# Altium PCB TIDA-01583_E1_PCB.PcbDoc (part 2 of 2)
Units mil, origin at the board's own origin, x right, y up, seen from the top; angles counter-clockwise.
Board outline 2000 x 2400 mil, 4 copper layers (Top Layer, GND, PWR, Bottom Layer), stack 5.6 mil thick; 127 components, 58 nets, 301 pads, 119 vias.
Unrouted connection lines stored in the file: 16.
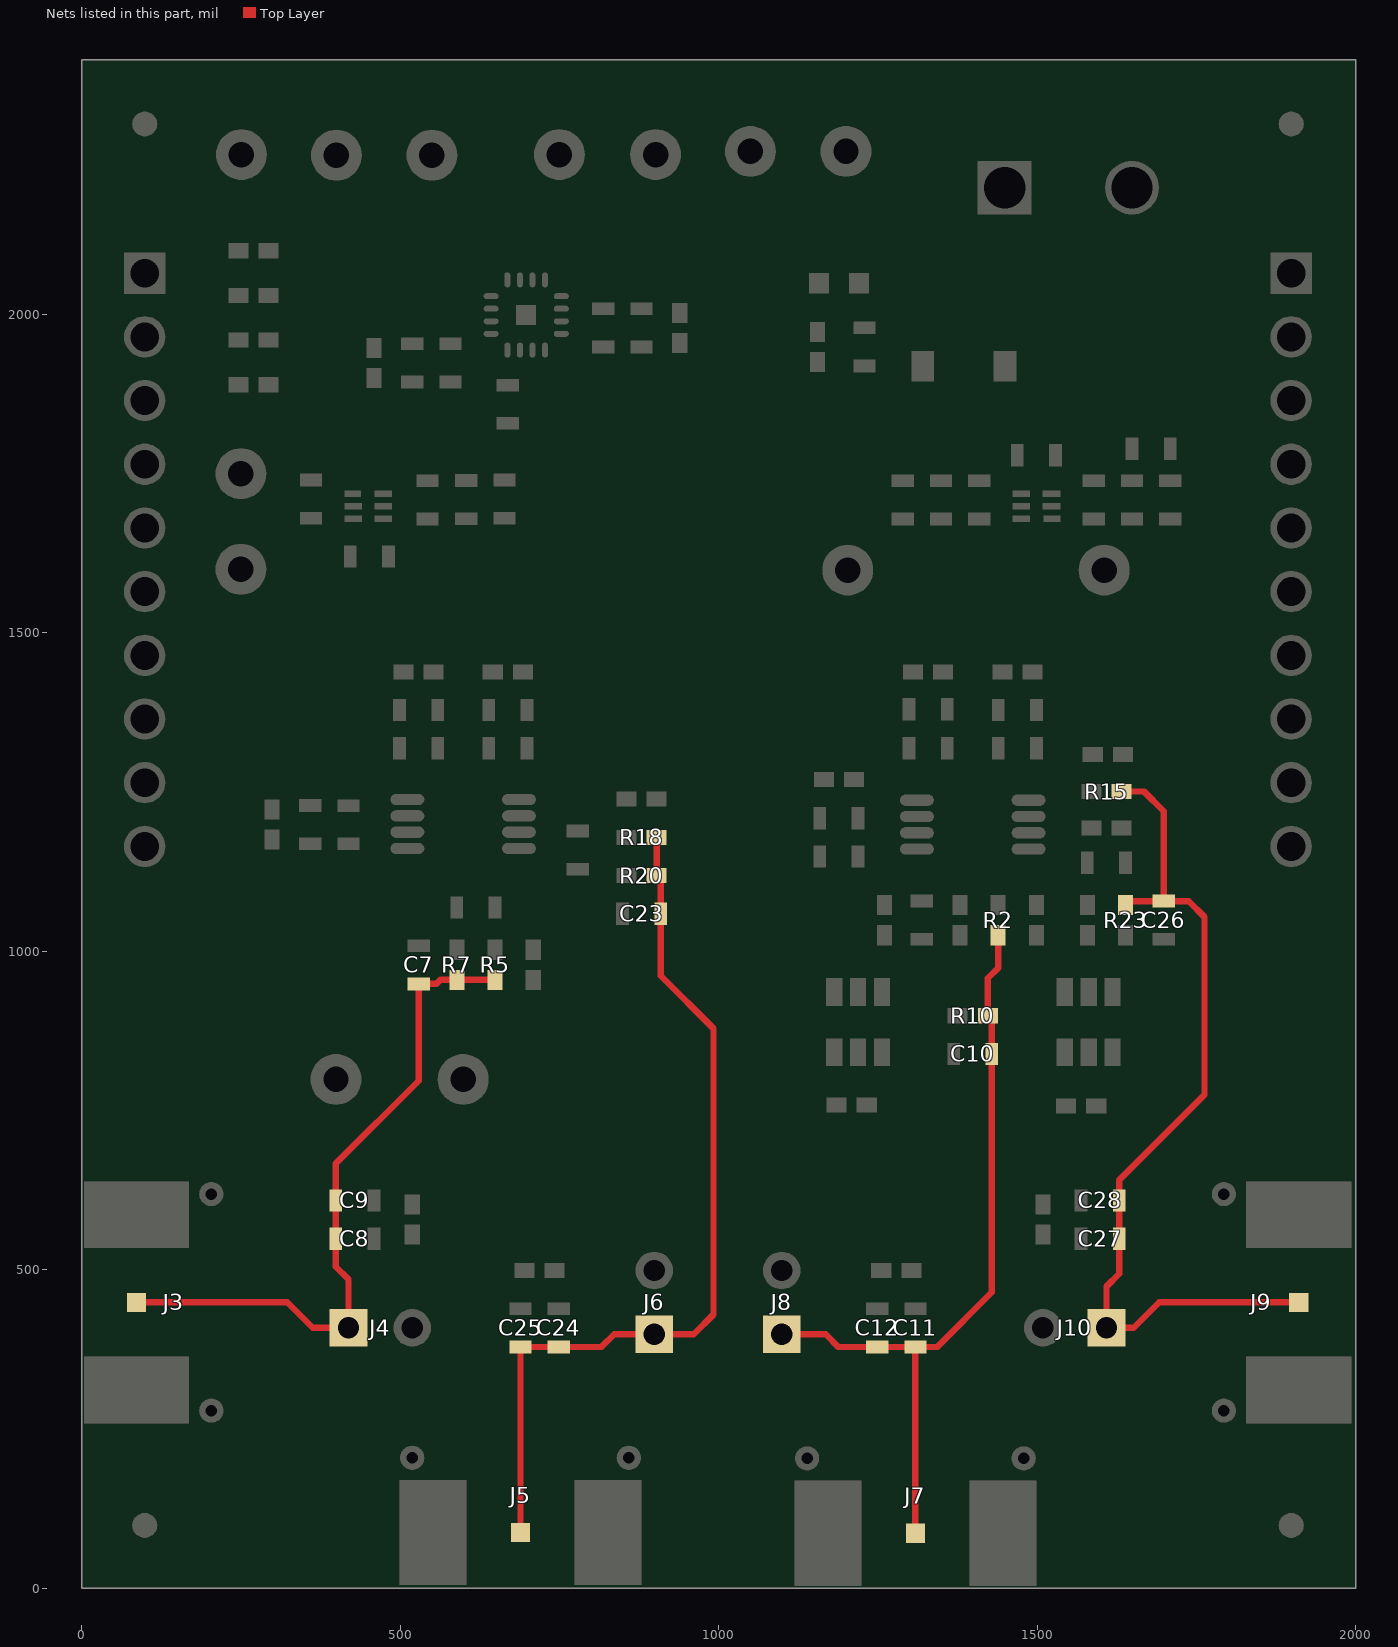
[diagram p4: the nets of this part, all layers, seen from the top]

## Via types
v1: diameter 24, hole 12, Top Layer to Bottom Layer, tented both sides, 118 vias
v2: diameter 19.68, hole 7.87, Top Layer to Bottom Layer, 1 vias

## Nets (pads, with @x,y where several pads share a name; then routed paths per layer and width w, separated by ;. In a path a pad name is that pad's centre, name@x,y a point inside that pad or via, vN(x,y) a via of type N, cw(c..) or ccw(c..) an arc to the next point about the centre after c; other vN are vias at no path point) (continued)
VOUT1: C7.1 C8.1 C9.1 J3.1 J4.1 R5.2 R7.2 | length 1074.3
  Top Layer w10: J3.1@86,448.99 323,448.99 363,408.99 J4.1@419,408.99 419,484.99 399,504.99 C8.1@399,548.99 C9.1@399,608.99 399,666.99 529,796.99 C7.1@529,948.99 557,948.99 563.38,955.37 R7.2@589,955.37 R5.2@649,955.37
VOUT2: C23.1 C24.1 C25.1 J5.1 J6.1 R18.2 R20.2 | length 1401.6
  Top Layer w10: J5.1@689,87.49 C25.1@689,378.99 C24.1@749,378.99 816,378.99 836,398.99 J6.1@899,398.99 961,398.99 992,429.99 992,878.99 909,961.99 C23.1@909,1058.99 909,1112.61 R20.2@902.62,1118.99 R18.2@902.62,1178.99
VOUT3: C10.1 C11.1 C12.1 J7.1 J8.1 R2.2 R10.2 | length 1236.2
  Top Layer w10: J8.1@1099,398.99 1168,398.99 1188,378.99 C12.1@1249,378.99 C11.1@1309,378.99 ; J7.1@1309,86.49 C11.1@1309,378.99 ; R2.2@1439,1025.37 1439,973.99 1422.62,957.61 R10.2@1422.62,898.99 1429,892.61 C10.1@1429,838.99 1429,464.99 1343,378.99 C11.1@1309,378.99
VOUT4: C26.1 C27.1 C28.1 J9.1 J10.1 R15.2 R23.2 | length 1384.4
  Top Layer w10: R15.2@1632.62,1251.02 1667.98,1251.02 1699,1219.99 C26.1@1699,1078.99 ; R23.2@1639,1072.61 1645.38,1078.99 C26.1@1699,1078.99 ; J9.1@1910.86,448.99 1692,448.99 1652,408.99 J10.1@1609,408.99 1609,473.99 1629,493.99 C27.1@1629,548.99 C28.1@1629,608.99 1629,640.99 1762.94,774.93 1762.94,1054.06 1738,1078.99 C26.1@1699,1078.99
pads on no net: FID1.1 FID2.1 FID3.1 FID4.1 J1.1 J1.2 J1.5 J1.7 J1.9 J1.10 J2.2 J2.3 J2.4 J2.5 J2.6 J2.7 J2.8 J2.9 J2.10 J3. J5. J7. J9. LBL1.0

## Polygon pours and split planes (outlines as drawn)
+6V5_IN on Top Layer "Top Layer-GND" (solid, pour order 49): 1132,1941.99 1273,1941.99 1281,1949.99 1317,1949.99 1340,1949.99 1349,1940.99 1370,1919.99 1370,1753.99 1370,1728.99 1365,1723.99 1324,1723.99 1152,1723.99 1112,1763.99 1112,1870.99 1112,1921.99 1132,1941.99
NetD2_2 on Top Layer "Top Layer-GND" (solid, pour order 50): 1128,2074.99 1128,1968.99 1139,1957.99 1140,1956.99 1161,1956.99 1167,1956.99 1178,1967.99 1178,1997.99 1178,2072.55 1174,2076.55 1167.56,2082.99 1142,2082.99 1136,2082.99
NetD1_2 on Top Layer "Top Layer-GND" (solid, pour order 51): 1399,2250.99 1399,1913.99 1426,1886.99 1491,1886.99 1502,1897.99 1506,1901.99 1506,2016.99 1506,2246.99 1497,2255.99 1489,2263.99 1454,2263.99 1412,2263.99 1399,2250.99
+6V5A on Top Layer "Top Layer-GND" (solid, pour order 52): 1455,1728.99 1485,1728.99 1489,1724.99 1490,1723.99 1490,1719.99 1490,1713.99 1489,1712.99 1485,1712.99 1449.99,1712.99 1445,1708 1445,1694.99 1445,1688.99 1449,1684.99 1449.76,1684.23 1461,1684.23 1489.76,1684.23 1491,1682.99 1492,1681.99 1492,1677.99 1492,1675.99 1490,1673.99 1482,1673.99 1446,1673.99 1434,1661.99 1432,1659.99 1371,1659.99 1336,1659.99 1326,1669.99 1326,1690.99 1329,1693.99 1331,1695.99 1350,1695.99 1412,1695.99 1445,1728.99
+5V0A_OUT on Top Layer "Top Layer-GND" (solid, pour order 53): 1512,1681.99 1557,1681.99 1566,1690.99 1571,1695.99 1598,1695.99 1666,1695.99 1672,1689.99 1673,1688.99 1673,1664.99 1673,1663.99 1666,1656.99 1663,1653.99 1604,1653.99 1519,1653.99 1512,1660.99
DAC_VDD on Top Layer "Top Layer-GND" (solid, pour order 56): 745,2013.99 792,2013.99 801,2022.99 814,2035.99 939,2035.99 946.5,2035.99 959.5,2022.99 959.5,1990.49 952,1982.99 913,1982.99 905,1990.99 903,1992.99 875,1992.99 776,1992.99 765,2003.99 740.62,2003.99 739,2005.61 739,2008.99 739,2011.99 741,2013.99 746,2013.99
OPA_VCC2 on Top Layer "Top Layer-GND" (solid, pour order 58): 1336.15,1167.99 1340,1164.14 1340,1148.99 1320,1128.99 1242,1128.99 1211,1128.99 1207,1132.99 1206,1133.99 1206,1226.99 1206,1243.99 1195,1254.99 1194,1255.99 1194,1284.99 1194,1290.99 1196,1292.99 1201,1297.99 1213,1297.99 1240,1297.99 1247,1290.99 1250,1287.99 1250,1256.99 1250,1190.99 1269,1171.99 1273,1167.99
OPA_VCC1 on Top Layer "Top Layer-GND" (solid, pour order 59): 537,1168.99 542,1163.99 542,1152.99 540,1150.99 528.32,1139.31 415,1139.31 284.68,1139.31 273,1150.99 273,1186.99 278,1191.99 280,1193.99 311,1193.99 317,1193.99 330,1180.99 347,1180.99 455,1180.99 467,1168.99
DAC_VIO on Top Layer "Top Layer-GND" (solid, pour order 64): 633,1974.99 652,1974.99 655,1971.99 655,1964.99 652,1961.99 631,1940.99 593,1940.99 487,1940.99 477,1930.99 453,1930.99 447,1930.99 443,1934.99 443,1964.99 447,1968.99 453,1974.99 624,1974.99
GND on Top Layer "Top Layer-GND" (solid, pour order 66): 509,1905.99 611,1905.99 624,1892.99 629,1887.99 629,1862.99 629,1853.99 612,1836.99 583,1836.99 507,1836.99 498,1845.99 498,1865.99 498,1894.99
GND on Top Layer "Top Layer-GND" (solid, pour order 67): 801,1960.99 899,1960.99 902,1957.99 902,1926.99 902,1888.99 893,1879.99 889,1875.99 856,1875.99 812,1875.99 800,1887.99 796,1891.99 796,1915.99 796,1955.99 801,1960.99
GND on Top Layer "Top Layer-GND" (solid, pour order 69): 1205,2092.99 1205,1973.99 1213,1965.99 1273,1965.99 1281,1973.99 1286,1978.99 1286,2034.99 1286,2089.99 1278,2097.99 1270,2105.99 1238,2105.99 1218,2105.99 1205,2092.99
GND on Top Layer "Top Layer-GND" (solid, pour order 70): 1220,1694.99 1304,1694.99 1310,1688.99 1310,1639.99 1303,1632.99 1302,1631.99 1272,1631.99 1253,1631.99 1231,1653.99 1215,1669.99 1215,1681.99 1215,1689.99
GND on Top Layer "Top Layer-GND" (solid, pour order 73): 1571,1808.99 1571,1728.99 1574,1725.99 1606,1725.99 1611,1730.99 1611,1755.99 1625,1769.99 1646,1769.99 1657.97,1769.99 1661.97,1773.99 1661.97,1809.99 1658.97,1812.99 1646.97,1824.99 1605.41,1824.99 1581,1824.99 1571,1814.99
+5V0A on Top Layer "Top Layer-GND" (solid, pour order 55): 1628,1749.99 1628,1730.61 1632.62,1725.99 1634.62,1723.99 1654,1723.99 1774,1723.99 1784,1733.99 1784,1811.99 1769,1826.99 1714,1826.99 1697,1809.99 1696,1808.99 1696,1790.99 1696,1769.99 1688,1761.99 1680,1753.99 1632,1753.99
GND on Top Layer "Top Layer-GND" (solid, pour order 74): 1690,1689.99 1690,1637.99 1700,1627.99 1742,1627.99 1754,1639.99 1754,1685.99 1745,1694.99 1720,1694.99 1695,1694.99
GND on Top Layer "Top Layer-GND" (solid, pour order 78): 1311,1398.99 1311,1299.99 1304,1292.99 1267.34,1292.99 1242,1318.33 1242,1342.99 1242,1390.61 1255.38,1403.99 1257.38,1405.99 1289,1405.99 1304,1405.99
GND on Top Layer "Top Layer-GND" (solid, pour order 85): 1618,1346.99 1618,1295.99 1622,1291.99 1624,1289.99 1664.97,1289.99 1675,1289.99 1683,1297.99 1685,1299.99 1685,1331.99 1685,1346.99 1682,1349.99 1672,1359.99 1654,1359.99 1626,1359.99 1619,1352.99 1618,1351.99 1618,1346.99
GND on Top Layer "Top Layer-GND" (solid, pour order 77): 1171,1227.64 1171,1128.64 1164,1121.64 1114.35,1121.64 1102,1133.99 1102,1171.64 1102,1219.27 1115.38,1232.64 1117.38,1234.64 1149,1234.64 1164,1234.64
GND on Top Layer "Top Layer-GND" (solid, pour order 76): 511,1397.64 511,1298.64 504,1291.64 454.35,1291.64 442,1303.99 442,1341.64 442,1389.27 455.38,1402.64 457.38,1404.64 489,1404.64 504,1404.64
GND on Top Layer "Top Layer-GND" (solid, pour order 75): 437.65,1216.84 338.65,1216.84 338.65,1274.64 349.84,1285.84 381.65,1285.84 429.27,1285.84 442.65,1272.46 444.65,1270.46 444.65,1238.84 444.65,1223.84
GND on Top Layer "Top Layer-GND" (solid, pour order 86): 685,1398.99 685,1286.99 670,1271.99 660,1261.99 660,1249.99 660,1240.99 667,1233.99 788.16,1233.99 793,1238.84 793,1278.99 793,1367.99 765,1395.99 755,1405.99 720,1405.99 692,1405.99
GND on Top Layer "Top Layer-GND" (solid, pour order 84): 886,1276.99 886,1225.99 890,1221.99 892,1219.99 932.97,1219.99 943,1219.99 951,1227.99 953,1229.99 953,1261.99 953,1276.99 950,1279.99 940,1289.99 922,1289.99 894,1289.99 887,1282.99 886,1281.99 886,1276.99
GND on Top Layer "Top Layer-GND" (solid, pour order 83): 865.62,1020.99 865.62,1071.99 861.62,1075.99 859.62,1077.99 818.65,1077.99 808.62,1077.99 800.62,1069.99 798.62,1067.99 798.62,1035.99 798.62,1020.99 801.62,1017.99 811.62,1007.99 829.62,1007.99 857.62,1007.99 864.62,1014.99 865.62,1015.99 865.62,1020.99
GND on Top Layer "Top Layer-GND" (solid, pour order 82): 491,992.37 542,992.37 546,996.37 548,998.37 548,1039.34 548,1049.37 540,1057.37 538,1059.37 506,1059.37 491,1059.37 488,1056.37 478,1046.37 478,1028.37 478,1000.37 485,993.37 486,992.37 491,992.37
GND on Top Layer "Top Layer-GND" (solid, pour order 81): 747,971.99 696,971.99 692,967.99 690,965.99 690,925.02 690,914.99 698,906.99 700,904.99 732,904.99 747,904.99 750,907.99 760,917.99 760,935.99 760,963.99 753,970.99 752,971.99 747,971.99
GND on Top Layer "Top Layer-GND" (solid, pour order 87): 1494,1404.64 1540.62,1404.64 1556,1389.27 1556,1305.99 1536,1285.99 1521,1270.99 1521,1249.99 1521,1239.99 1513,1231.99 1466,1231.99 1458,1239.99 1458,1268.99 1465,1275.99 1487,1297.99 1487,1298.64 1487,1397.64
GND on Top Layer "Top Layer-GND" (solid, pour order 88): 1352,858.8 1383,858.8 1387,854.8 1388,853.8 1388,833.8 1388,765.99 1375,752.99 1360.31,752.99 1348,765.31 1348,840.56 1348,854.8
GND on Top Layer "Top Layer-GND" (solid, pour order 80): 1270.62,775.61 1219.62,775.61 1215.62,771.61 1213.62,769.61 1213.62,728.65 1213.62,718.61 1221.62,710.61 1223.62,708.61 1255.62,708.61 1270.62,708.61 1273.62,711.61 1283.62,721.61 1283.62,739.61 1283.62,767.61 1276.62,774.61 1275.62,775.61 1270.62,775.61
GND on Top Layer "Top Layer-GND" (solid, pour order 79): 1630.94,773.8 1579.94,773.8 1575.94,769.8 1573.94,767.8 1573.94,726.84 1573.94,716.8 1581.94,708.8 1583.94,706.8 1615.94,706.8 1630.94,706.8 1633.94,709.8 1643.94,719.8 1643.94,737.8 1643.94,765.8 1636.94,772.8 1635.94,773.8 1630.94,773.8
GND on Top Layer "Top Layer-GND" (solid, pour order 89): 443,638.99 443,528.99 449,522.99 476,522.99 482,528.99 482,533.99 482,571.99 492,581.99 495,584.99 520,584.99 539,584.99 545,590.99 556,601.99 556,635.99 556,667.99 545,678.99 481,678.99 454,678.99 443,667.99
GND on Top Layer "Top Layer-GND" (solid, pour order 90): 769,452.99 769,426.99 764,421.99 634,421.99 603,452.99 603,557.29 623.71,577.99 677,577.99 699,577.99 711,565.99 713,563.99 713,516.99 713,472.99 727,458.99 728,457.99 754,457.99 764,457.99
GND on Top Layer "Top Layer-GND" (solid, pour order 91): 1229,454.99 1229,429.99 1237,421.99 1350,421.99 1367,438.99 1383,454.99 1383,514.99 1383,556.99 1356,583.99 1352,587.99 1307,587.99 1291.62,587.99 1281.62,577.99 1281.62,477.61 1281,476.99 1263,458.99 1246,458.99 1233,458.99
GND on Top Layer "Top Layer-GND" (solid, pour order 92): 1481,589.99 1487,583.99 1522,583.99 1545,583.99 1552,576.99 1554,574.99 1554,553.99 1554,530.99 1563,521.99 1582,521.99 1591,530.99 1592,531.99 1592,570.99 1592,666.93 1573.94,684.99 1569.94,688.99 1529,688.99 1490,688.99 1481,679.99
+5V0A on Top Layer "Top Layer-GND" (solid, pour order 62): 1567.97,954.96 1567.97,814.99 1583.97,798.99 1654.97,798.99 1658.97,798.99 1671.97,811.99 1682,822.02 1682,943.37 1664.38,960.99 1574,960.99
+5V0A on Top Layer "Top Layer-GND" (solid, pour order 61): 1206,958.99 1206,812.99 1214,804.99 1220,798.99 1222,798.99 1293,798.99 1297,798.99 1310,811.99 1316,817.99 1316,949.99 1299,966.99 1214,966.99
+5V0A on Top Layer "Top Layer-GND" (solid, pour order 96): 925,1967.99 994,1967.99 999,1962.99 1000,1961.99 1000,1926.99 1000,1904.99 989,1893.99 984.65,1889.64 956,1889.64 934.35,1889.64 925,1898.99 922,1901.99 922,1937.99 922,1964.99
+5V0A on Top Layer "Top Layer-GND" (solid, pour order 95): 313,1209.99 244,1209.99 239,1214.99 238,1215.99 238,1250.99 238,1272.99 249,1283.99 253.35,1288.35 282,1288.35 303.65,1288.35 313,1278.99 316,1275.99 316,1239.99 316,1212.99
+5V0A on Top Layer "Top Layer-GND" (solid, pour order 94): 1176.24,1257.24 1110.38,1257.24 1105.38,1262.24 1104.38,1263.24 1104.38,1298.24 1104.38,1320.24 1115.38,1331.24 1119.73,1335.59 1148.38,1335.59 1170.02,1335.59 1179.38,1326.24 1179.38,1260.37
GND on Top Layer "Top Layer-GND" (solid, pour order 71): 1386,1812.99 1386,1730.99 1390,1726.99 1421,1726.99 1452,1757.99 1463,1757.99 1480,1757.99 1483,1760.99 1486.6,1764.59 1486.6,1787.99 1486.6,1820.39 1480,1826.99 1473,1833.99 1416,1833.99 1396,1833.99 1387,1824.99 1386,1823.99 1386,1813.99
GND on Top Layer "Top Layer-GND" (solid, pour order 72): 375,1690 372,1693 343,1693 338,1688 338,1663 324,1649 308,1649 304,1645 304,1601 311,1594 343.59,1594 368,1594 375,1601
+6V5A2 on Top Layer "Top Layer-GND" (solid, pour order 54): 459,1728 459,1715 461,1713 467,1713 497,1713 499,1711 499,1687.39 496.6,1684.99 458.99,1684.99 458,1684 458,1674 459,1673 461,1671 475,1671 501,1671 513,1683 513,1715 523,1725 619,1725 623,1729 623,1757 618,1762 610,1770 514,1770 482,1770 465,1753 459,1747
GND on Top Layer "Top Layer-GND" (solid, pour order 57): 527,1688 527,1656 512,1641 491,1641 466,1641 463,1638 463,1598 466,1595 469,1592 512,1592 555,1592 568,1605 568,1634 568,1687 560,1695 558,1697 536,1697
+6V5_IN on Top Layer "Top Layer-GND" (solid, pour order 60): 584,1693 584,1624 600,1608 606,1602 670,1602 698,1602 709,1613 712,1616 712,1651.99 712,1687 706,1693 699,1700 689,1700 591,1700 584,1693
+3V3D on Top Layer "Top Layer-GND" (solid, pour order 68): 411,1917 472,1917 475,1914 477,1912 477,1877 477,1819.62 438.19,1780.81 438.19,1713.76 344,1713.76 329,1729 329,1778 341,1790 380,1829 380,1840 380,1886
GND on GND "Top Layer-GND" (solid, pour order 93): 77,-0.01 1908,-0.01 1998,89.99 1998,2291.94 1891,2398.94 104.9,2398.94 -0.04,2293.99 -0.98,2293.06 -0.98,77.97
+6V5_IN on PWR "Top Layer-GND" (solid, pour order 63): 1105,1895 1252,1895 1270,1877 1270,1754 1236,1720 1209,1693 1129,1693 1113,1693 992,1572 931,1511 751,1511 628,1511 583,1556 578,1561 578,1632 578,1658 606,1686 614,1694 659,1694 891.75,1694 1092.75,1895 1106,1895
+5V0A on PWR "Top Layer-GND" (solid, pour order 65): 916,1987 916,1898 942,1872 994,1872 1007,1885 1064,1942 1293,1942 1341,1894 1352,1883 1352,1660 1352,1573 1213,1434 335,1434 212,1311 212,985 304,893 316,881 549,881 1018,881 1208,691 1631,691 1681,691 1737,747 1829,839 1829,1030 1829,2048 1748,2129 1746,2131 1346,2131 979,2131 919,2071 916,2068 916,1986

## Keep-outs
Keep-Out Layer:
  the board outline again, w11.81

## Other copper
Top Layer:
  text ".Layer_Name" at 426,-1438.24 h60
GND:
  text ".Layer_Name" at 429,-1442.75 h60
PWR:
  text ".Layer_Name" at 429,-1437.75 h60
Bottom Layer:
  text ".Layer_Name" at 426,-1438.24 h60

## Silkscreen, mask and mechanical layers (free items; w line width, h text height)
Top Overlay:
  lines w6: 494,1659 540,1613 744.01,1613 764.01,1633 ; 689,1762 700,1773 895,1773 935,1733 ; 765,899.99 877,1011.99 1227,1011.99 ; 1112,933.99 1112,943.99 1147,978.99 1666,978.99 1684,996.99 ; 1500.51,1472.98 1500.51,1485.5 1522,1506.99 1549,1506.99 ; 1522,1337.99 1542,1337.99 1571,1366.99
  text ".Layer_Name" at 426,-1438.24 h60
Bottom Overlay:
  rectangle: 337,627 637,727
  text "TIDA-" at 937,645 h60
  text "E1" at 314,643 h60
  text ".Layer_Name" at 426,-1438.24 h60
Top Paste:
  text ".Layer_Name" at 426,-1438.24 h60
Bottom Paste:
  text ".Layer_Name" at 426,-1438.24 h60
Top Solder:
  text ".Layer_Name" at 426,-1438.24 h60
  text ".Layer_Name" at 426,-1438.24 h60
Bottom Solder:
  text ".Layer_Name" at 426,-1438.24 h60
Drill Guide:
  text ".Layer_Name" at 426,-1438.24 h60
M1 Board Outline:
  the board outline again, w11.81
M2 Board Dimensions:
  rectangle: -151,-854.75 -26,-729.75
  rectangle: -26,-979.75 349,-854.75
  lines w7: -151,-854.75 849,-854.75 ; -26,-979.75 -26,-729.75 ; 99,-979.75 99,-729.75 ; 349,-979.75 349,-729.75 ; 599,-979.75 599,-729.75 ; -151,-979.75 849,-979.75 849,-729.75 -151,-729.75 -151,-979.75
M3 3D STEP Top:
  text ".Layer_Name" at 426,-1438.24 h60
M4 3D STEP Bottom:
  text ".Layer_Name" at 426,-1438.24 h60
M5 Assembly Top:
  lines w10: -443,-1509.91 6157,-1509.91 ; -443,-1306.58 6159,-1306.58 ; -443,-1103.25 -443,-1713.25 3562,-1713.25 6159,-1713.25 6159,-1103.25 -442.5,-1103.25 -442.5,-1713.25 1133,-1713.25 ; 2022,-1713.25 2022,-1103.25 ; 3289,-1306.58 3289,-1103.25 ; 4129,-1306.58 4129,-1103.25 ; 4751,-1719.75 4751,-1516.91
  text "COMPONENTS MARKED 'DNP' SHOULD NOT BE POPULATED." at 1002.5,-898.25 h60
  text "ASSEMBLY VARIANT:" at 1002,-1013.75 h60
  text ".VariantName" at 2038,-1013.75 h60
  text "PCB VIEWED FROM TOP SIDE" at -379.5,-1235.41 h60
  text "BOARD #:" at 2097,-1235.41 h60
  text ".PRJ_Number" at 2642.5,-1235.41 h60
  text "REV:" at 3487,-1235.41 h60
  text ".PCB_Rev" at 3778.5,-1235.41 h60
  text "SVN REV:" at 4325,-1235.41 h60
  text ".VersionControl_RevNumber" at 4831,-1235.41 h60
  text ".Layer_Name" at 432,-1437.75 h60
  text "LAYER NAME =" at -380,-1438.75 h60
  text "TID #:" at 2097,-1438.75 h60
  text ".TID" at 2642.5,-1438.75 h60
  text "PLOT NAME =" at -379.5,-1644.08 h60
  text ".plot_File_Name" at 426,-1644.08 h60
  text "GENERATED    :" at 2099,-1644.08 h60
  text ".Print_Date" at 2968.5,-1644.08 h60
  text ".Print_Time" at 3697.5,-1644.08 h60
  text "TEXAS INSTRUMENTS" at 4962,-1644.08 h60
M6 Assembly Bottom:
  lines w10: -443.5,-1307.08 6158.5,-1307.08 ; -441.5,-1510.41 6158.5,-1510.41 ; 964.5,-1720.25 964.5,-1517.41 ; 1586.5,-1307.08 1586.5,-1103.75 ; 2426.5,-1307.08 2426.5,-1103.75 ; 3693.5,-1713.75 3693.5,-1103.75 ; 4582.5,-1713.75 6158,-1713.75 6158,-1103.75 -443.5,-1103.75 -443.5,-1713.75 2153.5,-1713.75 6158.5,-1713.75 6158.5,-1103.75
  text "COMPONENTS MARKED 'DNP' SHOULD NOT BE POPULATED." at 5951,-897.75 h60
  text ".VariantName" at 4907,-1013.75 h60
  text "ASSEMBLY VARIANT:" at 5946,-1013.75 h60
  text ".VersionControl_RevNumber" at 884.5,-1235.91 h60
  text "SVN REV:" at 1390.5,-1235.91 h60
  text ".PCB_Rev" at 1937,-1235.91 h60
  text "REV:" at 2228.5,-1235.91 h60
  text ".PRJ_Number" at 3073,-1235.91 h60
  text "BOARD #:" at 3618.5,-1235.91 h60
  text "PCB VIEWED FROM BOTTOM SIDE" at 6095,-1235.91 h60
  text ".Layer_Name" at 5201,-1437.75 h60
  text ".TID" at 3073,-1439.25 h60
  text "TID #:" at 3618.5,-1439.25 h60
  text "LAYER NAME =" at 6048,-1443.75 h60
  text "TEXAS INSTRUMENTS" at 753.5,-1644.58 h60
  text ".Print_Time" at 2018,-1644.58 h60
  text ".Print_Date" at 2747,-1644.58 h60
  text "GENERATED    :" at 3616.5,-1644.58 h60
  text ".plot_File_Name" at 5289.5,-1644.58 h60
  text "PLOT NAME =" at 6095,-1644.58 h60
M9 Title Sheet:
  drawing of 57 lines, arcs and shapes, not listed
  text "1" at 588.84,7456.75 h70
  text "2" at 3084.5,7456.75 h70
  text "3" at 5573.84,7456.75 h70
  text "4" at 8080.51,7456.75 h70
  text "5" at 10579.5,7456.75 h70
  text "6" at 13084.5,7456.75 h70
  text "A" at -567.5,6313.75 h70
  text "A" at 14232.5,6313.75 h70
  text "B" at -567.5,3933.75 h70
  text "B" at 14232.5,3933.75 h70
  text "C" at -567.5,1558.75 h70
  text "C" at 14232.5,1558.75 h70
  text "PROJECT TITLE:" at 11192.5,-302.25 h45
  text ".PRJ_Title" at 11242.5,-435.57 h70
  text "DESIGNED FOR:" at 11192.5,-603.25 h45
  text ".PRJ_Customer" at 11242.5,-743.25 h70
  text "D" at -567.5,-811.25 h70
  text "D" at 14232.5,-811.25 h70
  text "FILE NAME:" at 11192.5,-903.25 h45
  text ".PCB_File_Name_No_Path" at 11242.5,-1023.25 h70
  text "Texas Instruments (TI) and/or its licensors do not warrant the accuracy or completeness of this specification" at 6223,-1185.09 h45
  text "ENGINEER:" at 11192.5,-1193.25 h45
  text "LAYOUT BY:" at 12697.5,-1193.25 h45
  text "or any information contained therein. TI and/or its licensors do not warrant that this design will meet" at 6178.01,-1297.75 h45
  text ".PRJ_Engineer" at 11242.5,-1348.24 h70
  text ".PCB_Layout" at 12748,-1348.24 h70
  text "the specifications, will be suitable for your application or fit for any particular purpose, or will operate in" at 6178.01,-1410.42 h45
  text "ALTIUM DESIGNER VERSION:" at 12697.5,-1503.25 h45
  text "an implementation. TI and/or its licensors do not warrant that the design is production worthy. You should" at 6178.01,-1523.08 h45
  text "completely validate and test your design implementation to confirm the system functionality for your application." at 6223,-1635.75 h45
  text ".print_Scale" at 11242.5,-1636.57 h70
  text ".Application_BuildNumber" at 12748,-1636.57 h70
  text "1" at 588.84,-1843.25 h70
  text "2" at 3084.5,-1843.25 h70
  text "3" at 5573.84,-1843.25 h70
  text "4" at 8080.51,-1843.25 h70
  text "5" at 10579.5,-1843.25 h70
  text "6" at 13084.5,-1843.25 h70
M10 Fab Notes:
  drawing of 173 lines, arcs and shapes, not listed
  text "DESIGN INFORMATION" at 12227.02,5621.25 h60
  text "MIN. TRACK WIDTH:" at 11582.46,5441.25 h60
  text "8" at 12678.7,5441.26 h60
  text "MIL" at 12833.46,5441.25 h60
  text "MIL" at 12928,5317 h60
  text "MIN. CLEARANCE:" at 11582.46,5309.25 h60
  text "7.87" at 12618.7,5309.26 h60
  text "MIL" at 12917,5178 h60
  text "MIN. VIA PAD SIZE:" at 11582.46,5177.25 h60
  text "19.685" at 12539,5177.25 h60
  text "0.15mm (5.91MIL)" at 12277.46,5035.54 h60
  text "MINIMUM ANNULAR RING" at 11253.23,5031.26 h60
  text "EXTERNAL" at 13035,5031.25 h60
  text "PER" at 11453.23,4913.26 h60
  text "IPC-D-275 CLASS 2 LEVEL C" at 11673.23,4913.25 h60
  text "MIL, HOLES" at 13161.46,4800.97 h60
  text "+/-" at 12769,4800.25 h60
  text "+/-" at 13623,4800.25 h60
  text "REGISTRATION TOLERANCES:" at 11253.23,4795.25 h60
  text "METAL" at 12453,4795.25 h60
  text "5" at 13029.2,4795.26 h60
  text "3" at 13862.2,4795.26 h60
  text "MIL" at 13978.46,4795.25 h60
  text "+/-" at 13623,4682.25 h60
  text "HOLE SIZE TOLERANCE (UNLESS OTHERWISE SPECIFIED):" at 11253.23,4677.25 h60
  text "3" at 13862.2,4677.26 h60
  text "MIL" at 13978.46,4677.25 h60
  text "MATERIAL:" at 11178.46,4467.8 h60
  text "FR-4 High Tg" at 12164.9,4327.46 h60
  text "FR-408" at 11599.46,4318.89 h60
  text "OTHER" at 13087.46,4318.89 h60
  text "X" at 12010,4315.25 h60
  text "63 MIL (1.6mm) +/-10%" at 11919.56,4156.18 h60
  text "THICKNESS:" at 11253.23,4151.89 h60
  text "X" at 11791.4,4151.89 h60
  text "OTHER" at 13204.46,4151.89 h60
  text "TOLERANCE:" at 11253.23,3993.89 h60
  text "X" at 12092.53,3993.89 h60
  text "ANSI IPC-6012 TYPE 3 CLASS 2" at 12279.48,3993.89 h60
  text "OTHER +/-" at 12279.46,3837.89 h60
  text "BOW & TWIST:" at 11253.23,3680.89 h60
  text "X" at 12092.53,3680.89 h60
  text "ANSI IPC-6012 TYPE 3 CLASS 2" at 12279.48,3680.89 h60
  text "OTHER +/-" at 12279.46,3522.38 h60
  text "DRILLING:" at 11178.46,3383.89 h60
  text "REFERENCE:" at 11253.23,3266.89 h60
  text "X" at 11901.46,3266.89 h60
  text "AS SHOWN" at 12088.46,3266.89 h60
  text "X" at 12802.46,3266.89 h60
  text "NC_DRILL FILES" at 12939.46,3266.89 h60
  text "PTH COPPER THICKNESS:" at 11253.23,3108.89 h60
  text "X" at 12383.46,3108.89 h60
  text "20-30 um" at 12520.46,3108.89 h60
  text "OTHER" at 13237.46,3108.89 h60
  text "BOARD FINISH:" at 11178.46,2949.89 h60
  text "SILKSCREEN:" at 11333.68,2831.89 h60
  text "X" at 12282.46,2831.89 h60
  text "TOP" at 12408.46,2831.89 h60
  text "X" at 12792.46,2831.89 h60
  text "BOTTOM" at 12919.46,2831.89 h60
  text "SILKSCREEN COLOR:" at 11333.68,2664.89 h60
  text "X" at 12281.42,2664.89 h60
  text "WHITE" at 12408.46,2664.89 h60
  text "OTHER" at 12919.46,2664.89 h60
  text "X" at 12412.42,2505.69 h60
  text "GREEN" at 12539.46,2505.69 h60
  text "OTHER" at 13157.46,2505.69 h60
  text "SOLDER RESIST COLOR:" at 11333.68,2494.89 h60
  text "X" at 12412.42,2335.69 h60
  text "MATTE" at 12539.46,2335.69 h60
  text "SEMI-GLOSS" at 13157,2335.06 h60
  text "IMMERSION GOLD (ENIG)" at 12239.46,2147.18 h60
  text "ENEPIG" at 13577,2143.89 h60
  text "SURFACE FINISH:" at 11178.46,2142.89 h60
  text "X" at 12052.51,2142.89 h60
  text "IMM. TIN/SILVER OR EQUIV" at 11508,1985.89 h60
  text "OTHER" at 12939.46,1985.89 h60
  text "ARRAY/PANEL:" at 11178.46,1806.89 h60
  text "CUT AND TRIM PER M1 BOARD OUTLINE" at 12239.46,1802.61 h60
  text "N.C. ROUTE" at 12239.46,1650.89 h60
  text "X" at 12918.46,1650.89 h60
  text "V. SCORE" at 13105.46,1650.89 h60
  text "CERTIFICATION:" at 11178.46,1513.89 h60
  text "MATERIALS AND WORKMANSHIP FOR ALL PCBS" at 11903.46,1513.89 h60
  text "TO MEET OR EXCEED THE REQUIREMENTS OF:" at 11903.46,1415.89 h60
  text "X" at 11529.96,1279.39 h60
  text "ANSI IPC-A-600F CLASS ->" at 11668.96,1279.39 h60
  text "X" at 13308.02,1279.39 h60
  text "2" at 13426.96,1279.39 h60
  text "1" at 13111.96,1277.89 h60
  text "3" at 13780.96,1277.89 h60
  text "X" at 12344.02,1119.89 h60
  text "RoHS" at 12480.96,1119.89 h60
  text "OTHER" at 13125.36,1119.89 h60
  text "PER ORDER" at 13522.42,1119.89 h60
  text "ALL BOARDS MUST MEET OR EXCEED UL94-V0 REQUIREMENTS." at 11206,954.25 h60
  text "PCB MUST BEAR THE UL94V-0 UL REGISTERED MATERIAL ID NUMBER" at 11206,834.25 h60
  text "ADDITIONAL REQUIREMENTS:" at 11178.46,660.89 h60
  text "MICROSECTION:" at 11253.23,545.89 h60
  text "YES" at 12158.96,545.89 h60
  text "REQUIRED" at 13020.46,389.75 h60
  text "BARE BOARD ELEC. TEST:" at 11253.23,386.89 h60
  text "NONE" at 12558.96,386.89 h60
  text "X" at 12893.46,386.89 h60
  text "PER ORDER" at 13612.46,386.89 h60
M11 Gerber Information:
  lines w10: -443,-1509.91 6157,-1509.91 ; -443,-1306.58 6159,-1306.58 ; -443,-1103.25 -443,-1713.25 3562,-1713.25 6159,-1713.25 6159,-1103.25 -442.5,-1103.25 -442.5,-1713.25 1133,-1713.25 ; 2022,-1713.25 2022,-1103.25 ; 3289,-1306.58 3289,-1103.25 ; 4129,-1306.58 4129,-1103.25 ; 4751,-1719.75 4751,-1516.91
  text "ALL ARTWORK VIEWED FROM TOP SIDE" at -379.5,-1235.41 h60
  text "BOARD #:" at 2097,-1235.41 h60
  text ".PRJ_Number" at 2642.5,-1235.41 h60
  text "REV:" at 3487,-1235.41 h60
  text ".PCB_Rev" at 3778.5,-1235.41 h60
  text "SVN REV:" at 4325,-1235.41 h60
  text ".VersionControl_RevNumber" at 4831,-1235.41 h60
  text "LAYER NAME =" at -379.5,-1438.24 h60
  text "TID #:" at 2097,-1438.75 h60
  text ".TID" at 2642.5,-1438.75 h60
  text "PLOT NAME =" at -379.5,-1644.08 h60
  text ".plot_File_Name" at 426,-1644.08 h60
  text "GENERATED    :" at 2099,-1644.08 h60
  text ".Print_Date" at 2968.5,-1644.08 h60
  text ".Print_Time" at 3697.5,-1644.08 h60
  text "TEXAS INSTRUMENTS" at 4962,-1644.08 h60
M12 Stackup:
  drawing of 295 lines, arcs and shapes, not listed
  text "Layer" at 9562.5,7202.75 h60
  text "Name" at 9972.41,7202.75 h60
  text "Material" at 10902.16,7202.75 h60
  text "Thickness" at 11761.92,7202.75 h60
  text "Constant" at 12411.76,7202.75 h60
  text "Board Layer Stack" at 12981.62,7202.75 h60
  text "1" at 9562.5,7082.75 h60
  text "Top Overlay" at 9972.41,7082.75 h60
  text "2" at 9562.5,6962.75 h60
  text "Top Solder" at 9972.41,6962.75 h60
  text "Solder Resist" at 10902.16,6962.75 h60
  text "0.40mil" at 11761.92,6962.75 h60
  text "3.5" at 12411.76,6962.75 h60
  text "3" at 9562.5,6842.75 h60
  text "Top Layer" at 9972.41,6842.75 h60
  text "Copper" at 10902.16,6842.75 h60
  text "1.40mil" at 11761.92,6842.75 h60
  text "4" at 9562.5,6722.75 h60
  text "Dielectric 1" at 9972.41,6722.75 h60
  text "FR-4 High Tg" at 10902.16,6722.75 h60
  text "4.2" at 12411.76,6722.75 h60
  text "5" at 9562.5,6602.75 h60
  text "GND" at 9972.41,6602.75 h60
  text "Copper" at 10902.16,6602.75 h60
  text "1.40mil" at 11761.92,6602.75 h60
  text "6" at 9562.5,6482.75 h60
  text "Dielectric 2" at 9972.41,6482.75 h60
  text "FR-4 High Tg" at 10902.16,6482.75 h60
  text "4.2" at 12411.76,6482.75 h60
  text "7" at 9562.5,6362.75 h60
  text "PWR" at 9972.41,6362.75 h60
  text "Copper" at 10902.16,6362.75 h60
  text "1.40mil" at 11761.92,6362.75 h60
  text "8" at 9562.5,6242.75 h60
  text "Dielectric3" at 9972.41,6242.75 h60
  text "FR-4 High Tg" at 10902.16,6242.75 h60
  text "4.8" at 12411.76,6242.75 h60
  text "9" at 9562.5,6122.75 h60
  text "Bottom Layer" at 9972.41,6122.75 h60
  text "Copper" at 10902.16,6122.75 h60
  text "1.40mil" at 11761.92,6122.75 h60
  text "10" at 9562.5,6002.75 h60
  text "Bottom Solder" at 9972.41,6002.75 h60
  text "Solder Resist" at 10902.16,6002.75 h60
  text "0.40mil" at 11761.92,6002.75 h60
  text "3.5" at 12411.76,6002.75 h60
  text "11" at 9562.5,5882.75 h60
  text "Bottom Overlay" at 9972.41,5882.75 h60
M13 Component Bodies Top:
  text ".Layer_Name" at 426,-1438.24 h60
M14 Component Bodies Bottom:
  text ".Layer_Name" at 426,-1438.24 h60
M15 Courtyards Top:
  text ".Layer_Name" at 426,-1438.24 h60
M16 Courtyards Bottom:
  text ".Layer_Name" at 426,-1438.24 h60
Drill Drawing:
  lines w10: 2904.29,780.5 2937.62,797.17 2970.96,780.5 2954.29,813.83 2970.96,847.17 2937.62,830.5 2904.29,847.17 2920.96,813.83 2904.29,780.5 ; 2904.29,947.17 2920.96,947.17 2937.62,930.5 2954.29,947.17 2970.96,947.17 2954.29,963.83 2970.96,980.5 2954.29,980.5 2937.62,997.17 2920.96,980.5 2904.29,980.5 2920.96,963.83 2904.29,947.17 ; 2904.29,1080.5 2937.62,1097.17 2970.96,1080.5 2954.29,1113.83 2970.96,1147.17 2937.62,1130.5 2904.29,1147.17 2920.96,1113.83 2904.29,1080.5 ; 2904.29,1247.17 2920.96,1247.17 2920.96,1230.5 2954.29,1230.5 2954.29,1247.17 2970.96,1247.17 2970.96,1280.5 2954.29,1280.5 2954.29,1297.17 2920.96,1297.17 2920.96,1280.5 2904.29,1280.5 2904.29,1247.17 ; 2904.29,1380.5 2904.29,1397.17 2920.96,1413.83 2904.29,1430.5 2904.29,1447.17 2920.96,1447.17 2937.62,1430.5 2954.29,1447.17 2970.96,1447.17 2970.96,1430.5 2954.29,1413.83 2970.96,1397.17 2970.96,1380.5 2954.29,1380.5 2937.62,1397.17 2920.96,1380.5 2904.29,1380.5 ; 2904.29,1563.83 2937.62,1530.5 2970.96,1563.83 2937.62,1597.17 2904.29,1563.83 ; 2904.29,1697.17 2920.96,1697.17 2920.96,1680.5 2954.29,1680.5 2954.29,1697.17 2970.96,1697.17 2970.96,1730.5 2954.29,1730.5 2954.29,1747.17 2920.96,1747.17 2920.96,1730.5 2904.29,1730.5 2904.29,1697.17 ; 2917.62,793.83 2937.62,803.83 2957.62,793.83 2947.62,813.83 2957.62,833.83 2937.62,823.83 2917.62,833.83 2927.62,813.83 2917.62,793.83 ; 2917.62,953.83 2927.62,953.83 2937.62,943.83 2947.62,953.83 2957.62,953.83 2947.62,963.83 2957.62,973.83 2947.62,973.83 2937.62,983.83 2927.62,973.83 2917.62,973.83 2927.62,963.83 2917.62,953.83 ; 2917.62,1703.83 2927.62,1703.83 2927.62,1693.83 2947.62,1693.83 2947.62,1703.83 2957.62,1703.83 2957.62,1723.83 2947.62,1723.83 2947.62,1733.83 2927.62,1733.83 2927.62,1723.83 2917.62,1723.83 2917.62,1703.83
  lines w15: 2844.5,735.5 6723.47,735.5 ; 2844.5,1785.5 6723.47,1785.5 ; 3395.38,585.5 3395.38,1935.5 ; 4093.19,585.5 4093.19,1935.5 ; 5438.79,585.5 5438.79,1935.5 ; 5944.67,585.5 5944.67,1935.5 ; 2844.5,585.5 6723.47,585.5 6723.47,1935.5 2844.5,1935.5 2844.5,585.5
  text "DIMENSIONS ARE IN MILS" at 374,2649 h60
  text "Symbol" at 2934.5,1830.5 h72
  text "Hit Count" at 3440.38,1830.5 h72
  text "Finished Hole Size" at 4138.19,1830.5 h72
  text "Plated" at 5483.79,1830.5 h72
  text "Hole Type" at 5989.67,1830.5 h72
  text "1" at 3440.38,1680.5 h60
  text "7.87mil (0.200mm)" at 4138.19,1680.5 h60
  text "PTH" at 5483.79,1680.5 h60
  text "Round" at 5989.67,1680.5 h60
  text "2" at 3440.38,1530.5 h60
  text "64.96mil (1.650mm)" at 4138.19,1530.5 h60
  text "PTH" at 5483.79,1530.5 h60
  text "Round" at 5989.67,1530.5 h60
  text "8" at 3440.38,1380.5 h60
  text "18.00mil (0.457mm)" at 4138.19,1380.5 h60
  text "PTH" at 5483.79,1380.5 h60
  text "Round" at 5989.67,1380.5 h60
  text "8" at 3440.38,1230.5 h60
  text "33.47mil (0.850mm)" at 4138.19,1230.5 h60
  text "PTH" at 5483.79,1230.5 h60
  text "Round" at 5989.67,1230.5 h60
  text "13" at 3440.38,1080.5 h60
  text "40.00mil (1.016mm)" at 4138.19,1080.5 h60
  text "PTH" at 5483.79,1080.5 h60
  text "Round" at 5989.67,1080.5 h60
  text "20" at 3440.38,930.5 h60
  text "45.28mil (1.150mm)" at 4138.19,930.5 h60
  text "PTH" at 5483.79,930.5 h60
  text "Round" at 5989.67,930.5 h60
  text "118" at 3440.38,780.5 h60
  text "12.00mil (0.305mm)" at 4138.19,780.5 h60
  text "PTH" at 5483.79,780.5 h60
  text "Round" at 5989.67,780.5 h60
  text "170 Total" at 3440.38,630.5 h60
  text "DRILL TABLE" at 2968,391 h60
  text "FOR 7.87MIL DRILL +0/-7.87MIL" at 2963,255 h60
  text "FOR 12MIL DRILL +0/-12MIL" at 2961,125 h60
  text "FOR PTH DRILL +/-3MIL" at 2957,-6 h60
  text "NOTE:" at 2952,-132 h60
  text "12MIL Vias are Tented in both the sides." at 2945,-257 h60
  text "7.87MIL vias are not Tented." at 2942,-382 h60
  text "This is not an Impedance controlled board." at 2930,-506 h60
  text ".Layer_Name" at 426,-1438.24 h60
M17 Embedded Cavity:
  text ".Layer_Name" at 426,-1438.24 h60
M18 Embedded Assembly:
  text ".Layer_Name" at 426,-1438.24 h60
M19 Embedded Keepout:
  text ".Layer_Name" at 426,-1438.24 h60

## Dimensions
0,2400 to 2000,2400 on M2 Board Dimensions
0,0 to 0,2400 on M2 Board Dimensions
-151,-979.75 to 849,-979.75 on M2 Board Dimensions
